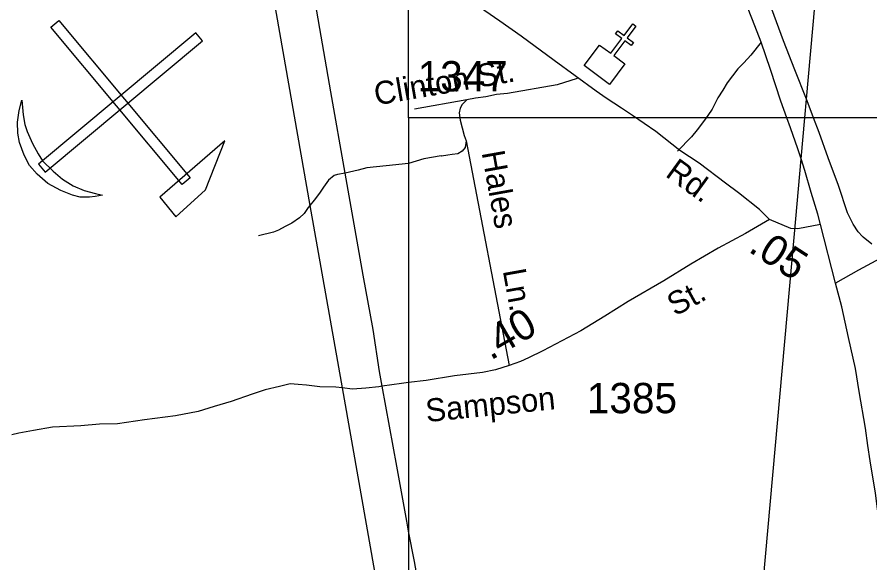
# Model space of a CAD drawing. Extents: x 2290055 to 2389491, y 66597 to 237875.
# Drawn here: x 2311511 to 2315029, y 190299 to 192551 of the extents above; entities that cross this region are included whole.
import ezdxf

# ---------------------------------------------------------------- set-up
doc = ezdxf.new("R2010")
doc.units = 0
for name, color, linetype in [('Exist Boundary Political Urban Extension UEB', 7, 'Continuous'), ('Exist Cultural Church CELL', 7, 'Continuous'), ('Exist Geographical Quarry CELL', 7, 'Continuous'), ('Exist Railroad Mainline', 7, 'Continuous'), ('Exist Road Non-System Type 51', 7, 'Continuous'), ('Exist Road Non-System Type 51 Label', 7, 'Continuous'), ('Exist Road Primary US UnDivided 4 Lane Attributed', 7, 'Continuous'), ('Exist Road Secondary Mileage Hundredths English Label', 7, 'Continuous'), ('Exist Road Secondary Type 51 Attributed', 7, 'Continuous'), ('Exist Road Secondary Type 51 Label', 7, 'Continuous'), ('Exist Road Secondary Type 51 Number Label', 7, 'Continuous'), ('Exist Utilities Electrical Transmission Line', 7, 'Continuous'), ('Map Preparation Inset Cut Line', 7, 'Continuous')]:
    doc.layers.add(name, color=color, linetype=linetype)

msp = doc.modelspace()

# ---------------------------------------------------------------- linework, layer by layer
at = {"layer": 'Exist Boundary Political Urban Extension UEB'}
for p, q in [((2312719.4, 191773.4), (2312852, 191021.5)), ((2312852, 191021.5), (2313126.6, 189465.2))]:
    msp.add_line(p, q, dxfattribs=at)
msp.add_lwpolyline([(2311983.7, 195161.2), (2311849.8, 195068.9), (2312243.8, 194309.5), (2312556, 192699.6), (2312719.4, 191773.4)], dxfattribs=at)
at = {"layer": 'Exist Cultural Church CELL'}
msp.add_lwpolyline([(2313914.3, 192435.6), (2313959.9, 192401.5), (2314005.6, 192462.5), (2313979.9, 192481.6), (2313989.5, 192494.4), (2314015.1, 192475.2), (2314051.2, 192523.4), (2314064, 192513.8), (2314028, 192465.6), (2314053.6, 192446.4), (2314044, 192433.7), (2314018.4, 192452.8), (2313972.7, 192391.9), (2314018.8, 192357.3), (2313954.9, 192272.1), (2313850.4, 192350.4)], close=True, dxfattribs=at)
at = {"layer": 'Exist Geographical Quarry CELL'}
for points in [[(2312225.3, 191887.7), (2312192.2, 191860.1), (2311649.9, 192509.6), (2311683, 192537.3)], [(2312276.2, 192453.3), (2312248.6, 192486.4), (2311599, 191944.1), (2311626.7, 191911)], [(2311864.1, 191816.4), (2311833.5, 191810.6), (2311809.6, 191807.4), (2311771.1, 191808.7), (2311739.6, 191815.8), (2311692, 191835.1), (2311637.8, 191864.7), (2311594, 191902.9), (2311561.9, 191939.1), (2311540, 191981.8), (2311521, 192033.9), (2311514.8, 192072), (2311513.5, 192117.2), (2311520.1, 192166), (2311530.3, 192208), (2311536.6, 192147.3), (2311543.8, 192108.1), (2311552.9, 192078.3), (2311575.3, 192029.1), (2311598.3, 191986.2), (2311616.1, 191957.8), (2311660.5, 191915.2), (2311698.3, 191881.7), (2311743.1, 191855.2), (2311788.6, 191836.1), (2311834.7, 191823.3)], [(2312099.8, 191807.5), (2312165.5, 191726.5), (2312288.1, 191837.8), (2312368, 192040.3)]]:
    msp.add_lwpolyline(points, close=True, dxfattribs=at)
at = {"layer": 'Exist Railroad Mainline'}
for points in [[(2313017.5, 191028.1), (2313006.5, 191089), (2312980.4, 191262.6), (2312939.5, 191486.1), (2312865, 191906.9), (2312805.6, 192242.4), (2312604.7, 193399.8)], [(2315036.9, 191613.7), (2315000.9, 191642.8), (2314998.8, 191645.2), (2314980.6, 191664.6), (2314960.2, 191696.4), (2314937.5, 191744), (2314900, 191855.5), (2314857.5, 191970.3), (2314819.3, 192074.6), (2314796.2, 192135.8), (2314778, 192184), (2314767.3, 192211.6), (2314720, 192333.3), (2314672.5, 192452.7), (2314606.1, 192637.7), (2314539.9, 192814.9)], [(2313189.4, 190087.4), (2313150.6, 190304.7), (2313126.6, 190430.4), (2313118.5, 190472.3), (2313077.6, 190697.9), (2313017.5, 191028.1)]]:
    msp.add_lwpolyline(points, dxfattribs=at)
at = {"layer": 'Exist Road Non-System Type 51'}
for points in [[(2314580.3, 192447), (2314538.4, 192393.3), (2314509.6, 192362.2), (2314484.6, 192337.2), (2314440.8, 192279.4), (2314422.1, 192248.7), (2314401.3, 192217.9), (2314379.1, 192171), (2314360.2, 192144.2), (2314354.4, 192135.8)], [(2313821.9, 192296.9), (2313738.9, 192271.6), (2313534.2, 192235.5), (2313488.3, 192231.7), (2313444.7, 192221.9), (2313402.9, 192216.3), (2313367.2, 192208.9), (2313347.9, 192190.1), (2313338.5, 192175.7), (2313335.3, 192155.6), (2313337.4, 192135.8)], [(2313367.2, 192208.9), (2313150.5, 192171.1)], [(2313337.4, 192135.8), (2313338.5, 192125.7), (2313347.7, 192094.1), (2313355, 192062.3), (2313363.9, 192040.7), (2313359, 192012.5), (2313347.6, 191998), (2313330, 191987.3), (2313306.1, 191984.4), (2313288.2, 191981.7), (2313262.4, 191976.6), (2313260.3, 191978.5), (2313188.8, 191965.7), (2313126.6, 191947.5)], [(2314354.4, 192135.8), (2314343.1, 192119.5), (2314316.4, 192086.4), (2314293.6, 192057.5), (2314235.9, 191997.2)], [(2313363.9, 192040.7), (2313540.7, 191113.4)], [(2313126.6, 191947.5), (2313125.5, 191947.2), (2313033.8, 191937.6), (2312954.2, 191928.4), (2312918.5, 191919), (2312865, 191906.9)], [(2312865, 191906.9), (2312865, 191906.9), (2312833.2, 191901.6), (2312819.3, 191897), (2312796.1, 191878.1), (2312775.2, 191849.3), (2312758.2, 191824.6), (2312737.3, 191795.8), (2312719.4, 191773.4)], [(2312719.4, 191773.4), (2312712.5, 191764.8), (2312695.5, 191740.1), (2312676.2, 191723.3), (2312645.1, 191700.1), (2312633.3, 191695.6), (2312617.6, 191687), (2312590.2, 191671.9), (2312568.5, 191663), (2312507.1, 191648.6)], [(2315103.4, 191569.8), (2315099.3, 191567.3), (2315054.2, 191545.5), (2314981.7, 191506.6), (2314887.8, 191452.9)]]:
    msp.add_lwpolyline(points, dxfattribs=at)
at = {"layer": 'Exist Road Primary US UnDivided 4 Lane Attributed'}
for points in [[(2314824.8, 191695), (2314814.5, 191738.1), (2314786.9, 191827), (2314761.3, 191918), (2314745.3, 191966.2), (2314731.8, 192006.9), (2314702.3, 192093.7), (2314686.9, 192135.8), (2314661.9, 192204.2), (2314618.7, 192334.5), (2314580.3, 192447), (2314544.6, 192539.6), (2314522.2, 192598.8), (2314486.6, 192689.4), (2314448.8, 192783.9), (2314410.4, 192894.4), (2314334.1, 193100.8)], [(2315133.9, 187977.6), (2315124.1, 188219.3), (2315121.2, 188493.3), (2315120.6, 188761.3), (2315115.2, 188997.2), (2315112.7, 189263.1), (2315115.8, 189587.4), (2315111, 189759.2), (2315104.5, 189973), (2315089.3, 190206.5), (2315076.4, 190330), (2315069.3, 190457.8), (2315052.2, 190587.2), (2315030.9, 190720.4), (2315020.4, 190784), (2315011.5, 190855.6), (2314985.5, 191006.6), (2314969.7, 191102), (2314940.7, 191228.9), (2314913.6, 191355.9), (2314887.8, 191452.9), (2314824.8, 191695)]]:
    msp.add_lwpolyline(points, dxfattribs=at)
at = {"layer": 'Exist Road Secondary Type 51 Attributed'}
for points in [[(2314615.2, 191716.2), (2314573.6, 191756.5), (2314487.6, 191826.4), (2314433.2, 191866.2), (2314324.4, 191948.6), (2314244.9, 192000.1), (2314146.6, 192078.4), (2314050.3, 192145.4), (2314004.3, 192174.7), (2313941.6, 192216.5), (2313899.7, 192245.8), (2313726.9, 192371.2), (2313590.9, 192471.8), (2313502.4, 192534.3), (2313401.5, 192604.3), (2313337, 192657.8), (2313205.9, 192751.3), (2313126.6, 192804.1), (2313065.6, 192851.1), (2312932.5, 192950.3), (2312855.8, 193010.3), (2312772.3, 193066.5)], [(2314615.2, 191716.2), (2314515.5, 191658.2), (2314403.8, 191597.8), (2314290.4, 191531.2), (2314179.1, 191462.8), (2314031.5, 191377.6), (2313935.3, 191316.9), (2313837, 191256.2), (2313680.1, 191174.6), (2313621.5, 191145.3), (2313588, 191130.6), (2313540.7, 191113.4), (2313485.4, 191095.2), (2313431.8, 191085.1), (2313316.3, 191070.5), (2313199, 191051.8), (2313126.6, 191043.3), (2313097.4, 191039.8), (2313017.5, 191028.1)], [(2314824.8, 191695), (2314732.3, 191676.9), (2314703, 191679), (2314615.2, 191716.2)], [(2313017.5, 191028.1), (2313003.9, 191026.1), (2312950.2, 191020), (2312894.3, 191015.8), (2312852, 191021.5), (2312825.9, 191025), (2312759.8, 191026.4), (2312705.6, 191032.3), (2312671.2, 191034.9), (2312637.3, 191037.6), (2312593.7, 191027.8), (2312534.3, 191013.5), (2312480.9, 190995.4), (2312394.1, 190965.9), (2312324.9, 190945.2), (2312257.7, 190924.5), (2312164.3, 190906.8), (2312037, 190889.7), (2311925.6, 190873.3), (2311851.6, 190872.4), (2311773.8, 190865.3), (2311658, 190858.7), (2311578.5, 190845.5), (2311518.9, 190835.2), (2311490.3, 190828)]]:
    msp.add_lwpolyline(points, dxfattribs=at)
at = {"layer": 'Exist Utilities Electrical Transmission Line'}
for p, q in [((2314717.5, 191656.4), (2314745.3, 191966.2)), ((2314324.5, 187272.3), (2314717.5, 191656.4))]:
    msp.add_line(p, q, dxfattribs=at)
for points in [[(2314767.3, 192211.6), (2314836.2, 192980.7), (2314435.5, 193106.8)], [(2314745.3, 191966.2), (2314760.5, 192135.8), (2314767.3, 192211.6)]]:
    msp.add_lwpolyline(points, dxfattribs=at)
at = {"layer": 'Map Preparation Inset Cut Line'}
for points in [[(2380407.7, 211640.5), (2380407.7, 192135.8), (2313126.6, 192135.8), (2313126.6, 211640.5), (2321069.7, 211640.5), (2345338.5, 211640.5)], [(2374088.6, 192135.8), (2313126.6, 192135.8), (2313126.6, 149726.2), (2353934.7, 149726.2), (2375181.1, 184193.5), (2380407.7, 192135.8)]]:
    msp.add_lwpolyline(points, close=True, dxfattribs=at)

# ---------------------------------------------------------------- texts
at = {"layer": 'Exist Road Non-System Type 51 Label'}
for s, rotation, p in [('Clinton St.', 9.8254, (2312992.4, 192186.1)), ('Hales', 280.1632, (2313427.3, 191992.2)), ('Ln.', 280.1632, (2313514.6, 191505.2))]:
    msp.add_text(s, height=95, rotation=rotation, dxfattribs=at).set_placement(p)
at = {"layer": 'Exist Road Secondary Mileage Hundredths English Label'}
for s, rotation, p in [('.05', 327.0841, (2314523.4, 191586.3)), ('.40', 30.2065, (2313464.8, 191133.2))]:
    msp.add_text(s, height=125, rotation=rotation, dxfattribs=at).set_placement(p)
at = {"layer": 'Exist Road Secondary Type 51 Label'}
for s, rotation, p in [('Rd.', 324.1109, (2314181.2, 191896.7)), ('St.', 28.7422, (2314225.9, 191314.9)), ('Sampson', 5.736, (2313201, 190880.1))]:
    msp.add_text(s, height=95, rotation=rotation, dxfattribs=at).set_placement(p)
at = {"layer": 'Exist Road Secondary Type 51 Number Label'}
for s, p in [('1347', (2313163.8, 192244.3)), ('1385', (2313861.7, 190916.9))]:
    msp.add_text(s, height=125, dxfattribs=at).set_placement(p)

doc.saveas('drawing.dxf')
